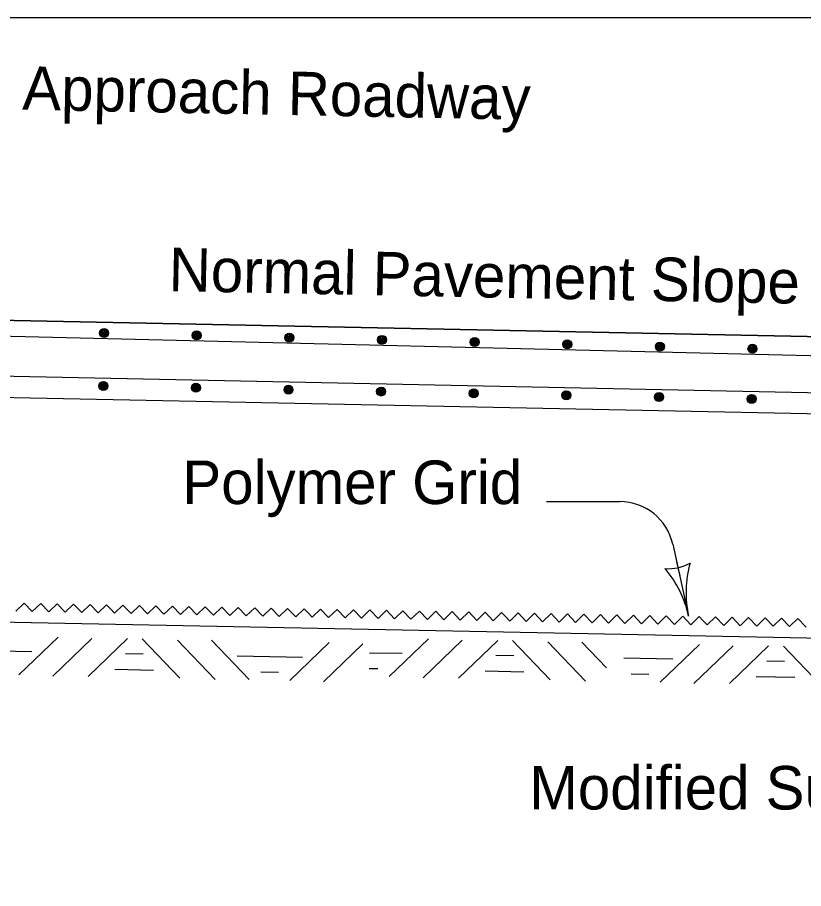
# Model space of a CAD drawing. Extents: x 10130 to 81668, y 5440 to 21644.
# Drawn here: x 17485.9 to 17774.7, y 9624 to 9944 of the extents above; entities that cross this region are included whole.
import ezdxf

# ---------------------------------------------------------------- set-up
doc = ezdxf.new("R2010")
doc.units = 0
for name, color, linetype in [('dsnStdBlockModified', 7, 'Continuous'), ('dsnStdBlockNotModified', 7, 'Continuous'), ('dsnStdBorder', 7, 'Continuous'), ('SheetBorder', 7, 'Continuous')]:
    doc.layers.add(name, color=color, linetype=linetype)

msp = doc.modelspace()

# ---------------------------------------------------------------- linework, layer by layer
at = {"layer": 'dsnStdBlockModified'}
msp.add_line((18198.1, 9797.36), (17466.58, 9812.52), dxfattribs=at)
at = {"layer": 'dsnStdBlockNotModified'}
for p, q in [((17680.34, 9766.17), (17707.15, 9766.17)), ((17726.68, 9750.48), (17732.49, 9724.11))]:
    msp.add_line(p, q, dxfattribs=at)
for centre, radius, start, end in [((17707.15, 9746.17), 20, 12.4314, 90), ((17725.25, 9757.01), 15.52, 264.685, 300.1517), ((17771.73, 9732.75), 40.18, 164.3459, 192.4183), ((17693.26, 9715.47), 40.18, 12.4183, 40.4908)]:
    msp.add_arc(centre, radius, start, end, dxfattribs=at)
at = {"layer": 'dsnStdBorder'}
for p, q in [((18176.88, 9818.81), (17466.62, 9833.07)), ((17466.62, 9833.07), (18176.88, 9818.81)), ((17466.59, 9827.31), (18198.18, 9809.65)), ((17466.05, 9804.71), (18215.16, 9789.67)), ((17467.19, 9804.69), (18215.16, 9789.67)), ((17728.1, 9744.03), (17729.23, 9738.92)), ((17466.62, 9722.28), (18283.21, 9705.89)), ((17500.84, 9716.33), (17486.42, 9702.48)), ((17513.28, 9715.86), (17498.86, 9702)), ((17526.29, 9715.82), (17511.87, 9701.96)), ((17531.7, 9715.71), (17545.56, 9701.29)), ((17544.7, 9715.22), (17558.56, 9700.8)), ((17557.16, 9715.2), (17571.01, 9700.78)), ((17600.37, 9714.33), (17585.95, 9700.48)), ((17612.81, 9713.86), (17598.39, 9700)), ((17636.91, 9715.69), (17622.49, 9701.84)), ((17649.35, 9715.22), (17634.93, 9701.36)), ((17662.36, 9715.18), (17647.94, 9701.33)), ((17667.77, 9715.07), (17681.63, 9700.65)), ((17680.77, 9714.59), (17694.63, 9700.16)), ((17693.23, 9714.56), (17702.33, 9705.09)), ((17736.44, 9713.69), (17722.02, 9699.84)), ((17748.88, 9713.22), (17734.46, 9699.36)), ((17761.89, 9713.18), (17747.47, 9699.33)), ((17767.3, 9713.07), (17781.16, 9698.65))]:
    msp.add_line(p, q, dxfattribs=at)
for points in [[(17516.23, 9827.98), (17516.5, 9828.53), (17516.81, 9829.38), (17517.69, 9829.52), (17518.47, 9829.36), (17519.15, 9828.77), (17519.05, 9827.95), (17518.88, 9827.08), (17518.17, 9826.7), (17517.43, 9826.66), (17516.5, 9827.21), (17516.45, 9827.85), (17516.71, 9828.71), (17517.3, 9829.4), (17518.12, 9829.34), (17518.76, 9828.75), (17518.8, 9827.97), (17518.59, 9827.11), (17518.1, 9827), (17517.5, 9826.85), (17516.8, 9827.29), (17516.85, 9827.92), (17517, 9828.64), (17517.43, 9829.15), (17518.14, 9828.85), (17518.53, 9828.28), (17518.53, 9827.55), (17518.12, 9827.38), (17517.67, 9827.18), (17517.12, 9827.56), (17517, 9828.1), (17517.29, 9828.57), (17517.82, 9828.58), (17518.19, 9828.3), (17518.3, 9827.81), (17518.09, 9827.58), (17517.79, 9827.45), (17517.37, 9827.73), (17517.3, 9828.08), (17517.52, 9828.41), (17517.8, 9828.34), (17517.98, 9828.08), (17517.95, 9827.74), (17517.71, 9827.76), (17517.59, 9828.06)], [(17550.26, 9827.16), (17550.53, 9827.7), (17550.84, 9828.56), (17551.72, 9828.69), (17552.5, 9828.54), (17553.18, 9827.95), (17553.07, 9827.13), (17552.91, 9826.26), (17552.2, 9825.88), (17551.46, 9825.83), (17550.53, 9826.39), (17550.48, 9827.03), (17550.74, 9827.89), (17551.32, 9828.57), (17552.15, 9828.52), (17552.79, 9827.93), (17552.83, 9827.15), (17552.62, 9826.28), (17552.13, 9826.18), (17551.53, 9826.02), (17550.83, 9826.46), (17550.88, 9827.1), (17551.03, 9827.82), (17551.45, 9828.32), (17552.17, 9828.02), (17552.56, 9827.46), (17552.56, 9826.73), (17552.15, 9826.56), (17551.7, 9826.35), (17551.14, 9826.73), (17551.03, 9827.28), (17551.32, 9827.74), (17551.85, 9827.76), (17552.22, 9827.49), (17552.33, 9826.99), (17552.12, 9826.76), (17551.82, 9826.64), (17551.4, 9826.91), (17551.32, 9827.26), (17551.55, 9827.58), (17551.83, 9827.51), (17552.01, 9827.26), (17551.98, 9826.91), (17551.74, 9826.93), (17551.62, 9827.24)], [(17584.28, 9826.34), (17584.56, 9826.89), (17584.87, 9827.74), (17585.75, 9827.87), (17586.52, 9827.72), (17587.21, 9827.13), (17587.1, 9826.31), (17586.94, 9825.44), (17586.23, 9825.06), (17585.49, 9825.01), (17584.56, 9825.57), (17584.51, 9826.21), (17584.77, 9827.07), (17585.36, 9827.76), (17586.18, 9827.69), (17586.82, 9827.11), (17586.86, 9826.33), (17586.65, 9825.46), (17586.15, 9825.35), (17585.56, 9825.21), (17584.86, 9825.64), (17584.91, 9826.27), (17585.06, 9827), (17585.48, 9827.5), (17586.2, 9827.2), (17586.59, 9826.64), (17586.59, 9825.91), (17586.18, 9825.74), (17585.73, 9825.53), (17585.17, 9825.91), (17585.06, 9826.46), (17585.35, 9826.93), (17585.88, 9826.93), (17586.25, 9826.66), (17586.36, 9826.17), (17586.15, 9825.94), (17585.85, 9825.81), (17585.43, 9826.09), (17585.35, 9826.44), (17585.58, 9826.76), (17585.86, 9826.69), (17586.04, 9826.44), (17586.01, 9826.1), (17585.77, 9826.12), (17585.65, 9826.42)], [(17618.31, 9825.52), (17618.59, 9826.06), (17618.9, 9826.92), (17619.78, 9827.05), (17620.56, 9826.89), (17621.24, 9826.31), (17621.14, 9825.49), (17620.97, 9824.62), (17620.26, 9824.23), (17619.53, 9824.19), (17618.59, 9824.75), (17618.54, 9825.38), (17618.8, 9826.25), (17619.39, 9826.93), (17620.21, 9826.87), (17620.85, 9826.29), (17620.89, 9825.5), (17620.68, 9824.64), (17620.18, 9824.53), (17619.59, 9824.38), (17618.89, 9824.82), (17618.94, 9825.45), (17619.09, 9826.17), (17619.51, 9826.68), (17620.23, 9826.38), (17620.62, 9825.82), (17620.62, 9825.08), (17620.21, 9824.92), (17619.76, 9824.71), (17619.2, 9825.09), (17619.09, 9825.64), (17619.38, 9826.1), (17619.91, 9826.12), (17620.28, 9825.85), (17620.39, 9825.35), (17620.18, 9825.12), (17619.88, 9825), (17619.46, 9825.27), (17619.39, 9825.62), (17619.61, 9825.94), (17619.89, 9825.87), (17620.07, 9825.61), (17620.04, 9825.27), (17619.8, 9825.29), (17619.68, 9825.6)], [(17652.34, 9824.7), (17652.62, 9825.25), (17652.92, 9826.1), (17653.81, 9826.23), (17654.58, 9826.07), (17655.27, 9825.49), (17655.16, 9824.67), (17655, 9823.8), (17654.29, 9823.41), (17653.56, 9823.37), (17652.62, 9823.93), (17652.57, 9824.56), (17652.83, 9825.42), (17653.42, 9826.11), (17654.24, 9826.05), (17654.88, 9825.47), (17654.92, 9824.68), (17654.71, 9823.82), (17654.21, 9823.71), (17653.62, 9823.56), (17652.92, 9824), (17652.96, 9824.63), (17653.12, 9825.35), (17653.54, 9825.86), (17654.26, 9825.56), (17654.65, 9825), (17654.65, 9824.26), (17654.24, 9824.1), (17653.79, 9823.89), (17653.23, 9824.27), (17653.13, 9824.82), (17653.41, 9825.28), (17653.94, 9825.29), (17654.31, 9825.02), (17654.42, 9824.52), (17654.21, 9824.3), (17653.91, 9824.17), (17653.49, 9824.45), (17653.42, 9824.79), (17653.64, 9825.12), (17653.93, 9825.05), (17654.1, 9824.79), (17654.07, 9824.46), (17653.83, 9824.47), (17653.71, 9824.77)], [(17686.37, 9823.88), (17686.65, 9824.42), (17686.95, 9825.27), (17687.84, 9825.41), (17688.61, 9825.25), (17689.3, 9824.67), (17689.19, 9823.84), (17689.03, 9822.98), (17688.32, 9822.59), (17687.58, 9822.55), (17686.65, 9823.1), (17686.6, 9823.74), (17686.86, 9824.6), (17687.44, 9825.29), (17688.27, 9825.23), (17688.91, 9824.65), (17688.95, 9823.86), (17688.74, 9823), (17688.24, 9822.89), (17687.65, 9822.74), (17686.95, 9823.18), (17686.99, 9823.81), (17687.15, 9824.53), (17687.57, 9825.04), (17688.28, 9824.74), (17688.68, 9824.17), (17688.68, 9823.44), (17688.27, 9823.28), (17687.82, 9823.07), (17687.26, 9823.45), (17687.15, 9823.99), (17687.44, 9824.46), (17687.97, 9824.47), (17688.34, 9824.2), (17688.45, 9823.7), (17688.24, 9823.48), (17687.94, 9823.35), (17687.52, 9823.63), (17687.45, 9823.97), (17687.67, 9824.3), (17687.95, 9824.23), (17688.13, 9823.97), (17688.1, 9823.63), (17687.86, 9823.65), (17687.74, 9823.95)], [(17720.4, 9823.05), (17720.68, 9823.6), (17720.98, 9824.46), (17721.87, 9824.59), (17722.64, 9824.43), (17723.33, 9823.84), (17723.22, 9823.02), (17723.06, 9822.16), (17722.35, 9821.77), (17721.61, 9821.73), (17720.68, 9822.28), (17720.63, 9822.92), (17720.89, 9823.78), (17721.47, 9824.47), (17722.3, 9824.41), (17722.94, 9823.82), (17722.98, 9823.04), (17722.77, 9822.18), (17722.27, 9822.07), (17721.68, 9821.92), (17720.98, 9822.36), (17721.02, 9822.99), (17721.17, 9823.71), (17721.6, 9824.22), (17722.31, 9823.92), (17722.71, 9823.36), (17722.71, 9822.62), (17722.3, 9822.45), (17721.85, 9822.25), (17721.29, 9822.63), (17721.18, 9823.17), (17721.46, 9823.64), (17722, 9823.65), (17722.37, 9823.38), (17722.48, 9822.88), (17722.27, 9822.65), (17721.97, 9822.53), (17721.55, 9822.8), (17721.48, 9823.15), (17721.69, 9823.48), (17721.98, 9823.41), (17722.16, 9823.15), (17722.13, 9822.81), (17721.89, 9822.83), (17721.77, 9823.13)], [(17754.44, 9822.23), (17754.71, 9822.78), (17755.01, 9823.63), (17755.9, 9823.76), (17756.67, 9823.61), (17757.36, 9823.02), (17757.25, 9822.2), (17757.09, 9821.33), (17756.38, 9820.95), (17755.64, 9820.9), (17754.71, 9821.46), (17754.66, 9822.1), (17754.92, 9822.96), (17755.5, 9823.65), (17756.33, 9823.59), (17756.97, 9823), (17757.01, 9822.22), (17756.8, 9821.36), (17756.31, 9821.25), (17755.71, 9821.1), (17755.01, 9821.54), (17755.05, 9822.17), (17755.2, 9822.89), (17755.63, 9823.4), (17756.34, 9823.1), (17756.74, 9822.53), (17756.73, 9821.8), (17756.33, 9821.64), (17755.88, 9821.43), (17755.32, 9821.81), (17755.22, 9822.35), (17755.49, 9822.82), (17756.03, 9822.83), (17756.4, 9822.56), (17756.51, 9822.06), (17756.29, 9821.83), (17756, 9821.71), (17755.58, 9821.98), (17755.51, 9822.33), (17755.73, 9822.66), (17756.01, 9822.59), (17756.19, 9822.33), (17756.16, 9821.99), (17755.92, 9822.01), (17755.8, 9822.31)], [(17518.95, 9808.51), (17518.69, 9809.07), (17518.42, 9809.94), (17517.54, 9810.11), (17516.77, 9809.99), (17516.05, 9809.43), (17516.13, 9808.61), (17516.25, 9807.74), (17516.94, 9807.32), (17517.68, 9807.24), (17518.63, 9807.76), (17518.71, 9808.39), (17518.49, 9809.26), (17517.94, 9809.98), (17517.11, 9809.95), (17516.44, 9809.39), (17516.37, 9808.62), (17516.54, 9807.74), (17517.03, 9807.61), (17517.62, 9807.44), (17518.34, 9807.85), (17518.32, 9808.47), (17518.2, 9809.2), (17517.8, 9809.73), (17517.08, 9809.46), (17516.65, 9808.92), (17516.63, 9808.18), (17517.02, 9808), (17517.47, 9807.77), (17518.04, 9808.13), (17518.17, 9808.67), (17517.91, 9809.15), (17517.38, 9809.18), (17517, 9808.93), (17516.86, 9808.43), (17517.06, 9808.2), (17517.36, 9808.06), (17517.79, 9808.32), (17517.88, 9808.66), (17517.68, 9808.99), (17517.38, 9808.94), (17517.2, 9808.69), (17517.2, 9808.35), (17517.45, 9808.36), (17517.59, 9808.65)], [(17552.98, 9807.83), (17552.72, 9808.39), (17552.45, 9809.26), (17551.57, 9809.42), (17550.8, 9809.3), (17550.09, 9808.75), (17550.16, 9807.92), (17550.28, 9807.05), (17550.98, 9806.64), (17551.71, 9806.56), (17552.66, 9807.07), (17552.75, 9807.71), (17552.53, 9808.58), (17551.97, 9809.29), (17551.14, 9809.27), (17550.47, 9808.71), (17550.4, 9807.93), (17550.57, 9807.06), (17551.07, 9806.93), (17551.66, 9806.75), (17552.37, 9807.16), (17552.35, 9807.8), (17552.23, 9808.52), (17551.83, 9809.04), (17551.11, 9808.78), (17550.68, 9808.23), (17550.66, 9807.5), (17551.05, 9807.32), (17551.5, 9807.09), (17552.07, 9807.44), (17552.2, 9807.98), (17551.95, 9808.46), (17551.41, 9808.5), (17551.03, 9808.24), (17550.89, 9807.75), (17551.09, 9807.51), (17551.39, 9807.38), (17551.82, 9807.63), (17551.91, 9807.97), (17551.71, 9808.31), (17551.42, 9808.25), (17551.23, 9808), (17551.24, 9807.67), (17551.48, 9807.67), (17551.62, 9807.97)], [(17587.01, 9807.15), (17586.76, 9807.71), (17586.49, 9808.57), (17585.61, 9808.74), (17584.84, 9808.62), (17584.12, 9808.06), (17584.19, 9807.24), (17584.31, 9806.37), (17585.01, 9805.95), (17585.74, 9805.88), (17586.7, 9806.39), (17586.78, 9807.03), (17586.56, 9807.89), (17586, 9808.61), (17585.18, 9808.58), (17584.51, 9808.03), (17584.44, 9807.25), (17584.6, 9806.38), (17585.1, 9806.25), (17585.69, 9806.07), (17586.41, 9806.48), (17586.39, 9807.11), (17586.27, 9807.84), (17585.86, 9808.36), (17585.14, 9808.09), (17584.72, 9807.55), (17584.69, 9806.82), (17585.09, 9806.64), (17585.53, 9806.41), (17586.11, 9806.76), (17586.23, 9807.3), (17585.98, 9807.78), (17585.44, 9807.81), (17585.06, 9807.56), (17584.93, 9807.07), (17585.13, 9806.83), (17585.43, 9806.69), (17585.86, 9806.95), (17585.94, 9807.3), (17585.74, 9807.63), (17585.45, 9807.57), (17585.26, 9807.32), (17585.27, 9806.98), (17585.52, 9806.99), (17585.65, 9807.28)], [(17621.04, 9806.47), (17620.79, 9807.03), (17620.52, 9807.89), (17619.64, 9808.06), (17618.87, 9807.94), (17618.15, 9807.38), (17618.23, 9806.56), (17618.35, 9805.69), (17619.04, 9805.27), (17619.77, 9805.19), (17620.73, 9805.7), (17620.81, 9806.34), (17620.59, 9807.21), (17620.03, 9807.93), (17619.21, 9807.9), (17618.54, 9807.35), (17618.47, 9806.57), (17618.64, 9805.7), (17619.13, 9805.56), (17619.72, 9805.39), (17620.44, 9805.79), (17620.42, 9806.43), (17620.3, 9807.15), (17619.9, 9807.68), (17619.18, 9807.41), (17618.75, 9806.87), (17618.73, 9806.14), (17619.12, 9805.95), (17619.56, 9805.72), (17620.14, 9806.08), (17620.27, 9806.62), (17620.01, 9807.1), (17619.47, 9807.13), (17619.09, 9806.88), (17618.96, 9806.38), (17619.16, 9806.15), (17619.46, 9806.01), (17619.89, 9806.26), (17619.97, 9806.61), (17619.77, 9806.94), (17619.48, 9806.89), (17619.29, 9806.64), (17619.3, 9806.3), (17619.55, 9806.31), (17619.68, 9806.6)], [(17655.08, 9805.78), (17654.83, 9806.34), (17654.56, 9807.21), (17653.67, 9807.38), (17652.9, 9807.26), (17652.18, 9806.7), (17652.26, 9805.88), (17652.38, 9805), (17653.07, 9804.58), (17653.81, 9804.51), (17654.76, 9805.02), (17654.84, 9805.66), (17654.62, 9806.53), (17654.07, 9807.24), (17653.24, 9807.22), (17652.58, 9806.66), (17652.5, 9805.88), (17652.67, 9805.01), (17653.16, 9804.88), (17653.75, 9804.7), (17654.47, 9805.11), (17654.45, 9805.75), (17654.34, 9806.47), (17653.93, 9807), (17653.21, 9806.73), (17652.79, 9806.18), (17652.76, 9805.45), (17653.15, 9805.27), (17653.6, 9805.04), (17654.17, 9805.4), (17654.3, 9805.94), (17654.04, 9806.41), (17653.51, 9806.45), (17653.13, 9806.19), (17652.99, 9805.7), (17653.19, 9805.46), (17653.49, 9805.33), (17653.92, 9805.58), (17654.01, 9805.93), (17653.81, 9806.26), (17653.51, 9806.2), (17653.33, 9805.96), (17653.34, 9805.61), (17653.58, 9805.62), (17653.72, 9805.92)], [(17689.11, 9805.1), (17688.85, 9805.66), (17688.58, 9806.53), (17687.71, 9806.69), (17686.93, 9806.57), (17686.22, 9806.02), (17686.29, 9805.19), (17686.41, 9804.32), (17687.11, 9803.9), (17687.84, 9803.82), (17688.79, 9804.34), (17688.88, 9804.98), (17688.66, 9805.85), (17688.1, 9806.56), (17687.27, 9806.53), (17686.61, 9805.98), (17686.53, 9805.2), (17686.7, 9804.33), (17687.2, 9804.19), (17687.79, 9804.02), (17688.5, 9804.43), (17688.48, 9805.06), (17688.37, 9805.79), (17687.96, 9806.31), (17687.24, 9806.05), (17686.81, 9805.5), (17686.79, 9804.77), (17687.18, 9804.58), (17687.63, 9804.36), (17688.2, 9804.71), (17688.33, 9805.25), (17688.08, 9805.73), (17687.54, 9805.76), (17687.16, 9805.51), (17687.02, 9805.02), (17687.23, 9804.78), (17687.52, 9804.64), (17687.95, 9804.9), (17688.04, 9805.24), (17687.84, 9805.58), (17687.55, 9805.52), (17687.36, 9805.27), (17687.37, 9804.93), (17687.61, 9804.94), (17687.75, 9805.23)], [(17723.14, 9804.42), (17722.89, 9804.97), (17722.62, 9805.84), (17721.74, 9806.01), (17720.97, 9805.89), (17720.25, 9805.34), (17720.32, 9804.51), (17720.44, 9803.64), (17721.14, 9803.22), (17721.87, 9803.14), (17722.83, 9803.66), (17722.91, 9804.29), (17722.69, 9805.16), (17722.13, 9805.88), (17721.31, 9805.85), (17720.64, 9805.3), (17720.57, 9804.52), (17720.74, 9803.65), (17721.23, 9803.52), (17721.82, 9803.34), (17722.53, 9803.75), (17722.52, 9804.38), (17722.4, 9805.11), (17721.99, 9805.63), (17721.27, 9805.36), (17720.85, 9804.81), (17720.82, 9804.08), (17721.22, 9803.9), (17721.66, 9803.67), (17722.24, 9804.03), (17722.36, 9804.57), (17722.11, 9805.05), (17721.57, 9805.08), (17721.19, 9804.83), (17721.06, 9804.34), (17721.26, 9804.1), (17721.56, 9803.96), (17721.99, 9804.22), (17722.07, 9804.56), (17721.87, 9804.9), (17721.58, 9804.84), (17721.39, 9804.59), (17721.4, 9804.25), (17721.65, 9804.26), (17721.78, 9804.55)], [(17757.17, 9803.73), (17756.92, 9804.29), (17756.65, 9805.16), (17755.77, 9805.33), (17755, 9805.21), (17754.28, 9804.65), (17754.36, 9803.82), (17754.48, 9802.96), (17755.17, 9802.54), (17755.9, 9802.46), (17756.86, 9802.97), (17756.94, 9803.61), (17756.72, 9804.48), (17756.16, 9805.2), (17755.34, 9805.17), (17754.67, 9804.61), (17754.6, 9803.83), (17754.77, 9802.96), (17755.26, 9802.83), (17755.85, 9802.65), (17756.57, 9803.06), (17756.55, 9803.69), (17756.43, 9804.42), (17756.03, 9804.95), (17755.3, 9804.68), (17754.88, 9804.14), (17754.86, 9803.4), (17755.25, 9803.22), (17755.69, 9802.99), (17756.27, 9803.34), (17756.4, 9803.89), (17756.14, 9804.37), (17755.6, 9804.4), (17755.22, 9804.14), (17755.09, 9803.65), (17755.29, 9803.41), (17755.59, 9803.28), (17756.02, 9803.53), (17756.1, 9803.88), (17755.9, 9804.21), (17755.61, 9804.16), (17755.42, 9803.91), (17755.43, 9803.57), (17755.68, 9803.57), (17755.81, 9803.87)], [(17485.3, 9725.91), (17488.39, 9728.88), (17491.35, 9725.79), (17494.44, 9728.76), (17497.4, 9725.67), (17500.49, 9728.63), (17503.45, 9725.55), (17506.54, 9728.51), (17509.5, 9725.43), (17512.59, 9728.39), (17515.55, 9725.31), (17518.64, 9728.27), (17520.12, 9726.73)], [(17520.12, 9726.73), (17521.6, 9725.19), (17524.68, 9728.15), (17527.65, 9725.06), (17530.73, 9728.03), (17533.69, 9724.94), (17536.78, 9727.91), (17539.74, 9724.82), (17542.83, 9727.79), (17545.79, 9724.7), (17548.88, 9727.66), (17551.84, 9724.58), (17554.93, 9727.54), (17557.89, 9724.46), (17560.97, 9727.42), (17563.94, 9724.34), (17567.02, 9727.3), (17569.99, 9724.22), (17573.07, 9727.18), (17576.04, 9724.09), (17579.12, 9727.05), (17582.09, 9723.97), (17585.17, 9726.93), (17588.13, 9723.85), (17591.22, 9726.81), (17592.7, 9725.27)], [(17592.7, 9725.27), (17594.18, 9723.73), (17597.27, 9726.69), (17600.23, 9723.61), (17603.32, 9726.57), (17606.28, 9723.48), (17609.37, 9726.45), (17612.33, 9723.36), (17615.41, 9726.33), (17618.38, 9723.24), (17621.46, 9726.21), (17624.43, 9723.12), (17627.51, 9726.08), (17630.48, 9723), (17633.56, 9725.96), (17636.52, 9722.88), (17639.61, 9725.84), (17642.57, 9722.76), (17645.66, 9725.72), (17648.62, 9722.64), (17651.71, 9725.6), (17654.67, 9722.51), (17657.76, 9725.48), (17660.72, 9722.39), (17663.8, 9725.36), (17665.29, 9723.81)], [(17665.29, 9723.81), (17666.77, 9722.27), (17669.85, 9725.24), (17672.82, 9722.15), (17675.9, 9725.11), (17678.87, 9722.03), (17681.95, 9724.99), (17684.91, 9721.91), (17688, 9724.87), (17690.96, 9721.79), (17694.05, 9724.75), (17697.01, 9721.67), (17700.1, 9724.63), (17703.06, 9721.54), (17706.15, 9724.51), (17709.11, 9721.42), (17712.19, 9724.39), (17715.16, 9721.3), (17718.24, 9724.26), (17721.21, 9721.18), (17724.29, 9724.14), (17727.26, 9721.06), (17730.34, 9724.02), (17733.3, 9720.94), (17736.39, 9723.9), (17737.87, 9722.36)], [(17737.87, 9722.36), (17739.35, 9720.82), (17742.43, 9723.78), (17745.4, 9720.69), (17748.48, 9723.66), (17751.45, 9720.57), (17754.54, 9723.54), (17757.5, 9720.45), (17760.58, 9723.42), (17763.54, 9720.33), (17766.63, 9723.29), (17769.59, 9720.21), (17772.68, 9723.17), (17775.65, 9720.08)], [(17473.09, 9711.41), (17491.15, 9711.05)], [(17525.62, 9710.33), (17532.15, 9710.2)], [(17615.19, 9710.65), (17627.22, 9710.41)], [(17566.63, 9709.53), (17590.68, 9709.05)], [(17661.69, 9709.7), (17668.22, 9709.56)], [(17708.69, 9708.78), (17726.75, 9708.41)], [(17761.22, 9707.7), (17767.76, 9707.57)], [(17521.67, 9704.56), (17535.86, 9704.27)], [(17575.27, 9703.56), (17581.8, 9703.43)], [(17615.07, 9704.85), (17618.34, 9704.79)], [(17657.74, 9703.92), (17671.93, 9703.63)], [(17711.34, 9702.92), (17717.87, 9702.79)], [(17757.28, 9701.92), (17771.47, 9701.63)]]:
    msp.add_lwpolyline(points, dxfattribs=at)
for centre in [(17517.75, 9828.04), (17551.78, 9827.22), (17585.81, 9826.4), (17619.84, 9825.58), (17653.87, 9824.76), (17687.9, 9823.93), (17721.93, 9823.11), (17755.96, 9822.29), (17517.43, 9808.64), (17551.46, 9807.96), (17585.49, 9807.27), (17619.52, 9806.59), (17653.56, 9805.91), (17687.59, 9805.22), (17721.62, 9804.54), (17755.65, 9803.86)]:
    msp.add_circle(centre, 1.65, dxfattribs=at)
at = {"layer": 'SheetBorder'}
msp.add_lwpolyline([(17332.52, 9944.02), (20467.53, 9944.02), (20467.53, 7924.02), (17332.52, 7924.02)], close=True, dxfattribs=at)

# ---------------------------------------------------------------- texts
at = {"layer": 'dsnStdBlockNotModified'}
for s, p in [('Approach Roadway', (17487.58, 9910.13)), ('Normal Pavement Slope', (17541.38, 9843.49))]:
    msp.add_text(s, height=16, rotation=358.8502, dxfattribs=at).set_placement(p)
for s, p in [('Polymer Grid', (17546.5, 9765.24)), ('Modified Subbase', (17673.98, 9653.04))]:
    msp.add_text(s, height=16, dxfattribs=at).set_placement(p)

doc.saveas('drawing.dxf')
